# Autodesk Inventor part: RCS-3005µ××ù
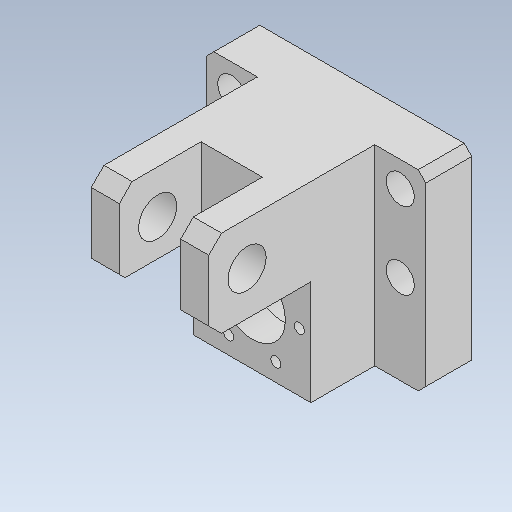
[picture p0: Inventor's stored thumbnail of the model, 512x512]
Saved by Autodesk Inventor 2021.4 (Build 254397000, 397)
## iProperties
Created: 2019-12
Part Number: RCS-3005µ××ù
Material: Ogólny
Document SubType Name: Modeling
Designer: user
Density: 1 g/cm^3
Appearance: Domyślna
Author: user
Revision Number: ÈÎºÎ
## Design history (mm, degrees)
feature "Body.7"
node "Bryła1"
